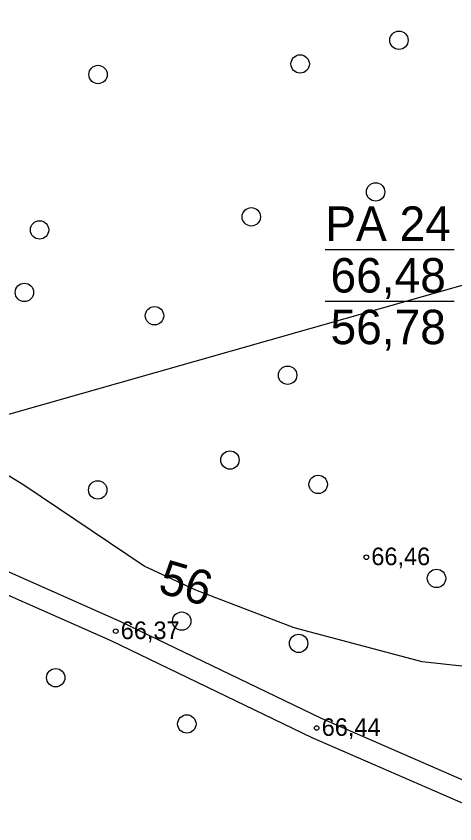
# Model space of a CAD drawing. Extents: x 532503 to 539665, y 6557663 to 6561526.
# Drawn here: x 534640.9 to 534702, y 6559686.6 to 6559799.2 of the extents above; entities that cross this region are included whole.
import ezdxf

# ---------------------------------------------------------------- set-up
doc = ezdxf.new("R2010")
doc.units = 0
for name, color, linetype in [('GEOLPUNKT', 7, 'Continuous'), ('HALJASTUS', 7, 'Continuous'), ('KORGUS-EH2000', 7, 'Continuous'), ('Lamami horisontaal_EH2000', 7, 'Continuous'), ('Lõige', 7, 'Continuous'), ('TEE', 7, 'Continuous')]:
    doc.layers.add(name, color=color, linetype=linetype)

# ---------------------------------------------------------------- blocks, each defined once
blk = doc.blocks.new('METS')
at = {"layer": 'HALJASTUS'}
blk.add_circle((0, 0), 0.8, dxfattribs=at)

msp = doc.modelspace()

# ---------------------------------------------------------------- linework, layer by layer
at = {"layer": 'GEOLPUNKT'}
for p, q in [((534683.91, 6559766.66), (534701.91, 6559766.66)), ((534683.91, 6559759.46), (534701.91, 6559759.46))]:
    msp.add_line(p, q, dxfattribs=at)
at = {"layer": 'KORGUS-EH2000'}
for centre in [(534689.66, 6559723.77), (534654.76, 6559713.47), (534682.74, 6559699.98)]:
    msp.add_circle(centre, 0.32, dxfattribs=at)
at = {"layer": 'Lamami horisontaal_EH2000'}
msp.add_lwpolyline([(534790.42, 6559711.19), (534772.61, 6559709.67), (534754.79, 6559708.12), (534736.98, 6559707), (534719.16, 6559707.01), (534715.24, 6559707.24), (534697.43, 6559709.2), (534679.62, 6559713.92), (534665.92, 6559719.18), (534658.73, 6559722.53), (534641.96, 6559733.8), (534636.15, 6559737.35)], dxfattribs=at)
at = {"layer": 'Lõige'}
msp.add_lwpolyline([(533917.43, 6559650.43), (533949.04, 6559659.85), (534215.74, 6559786.31), (534470.46, 6559695.5), (534707.91, 6559763.06), (534929.16, 6559826.01), (535198.18, 6559814.49), (535305.66, 6559887.85), (535520.8, 6559960.87), (535543.92, 6559971)], dxfattribs=at)
at = {"layer": 'TEE'}
for points in [[(534461.08, 6559790.53), (534478.84, 6559786.97), (534536.82, 6559761.75), (534575.75, 6559749.46), (534599.95, 6559739.48), (534655.41, 6559714.82), (534683.38, 6559701.33), (534712.77, 6559688.53)], [(534713.08, 6559685.13), (534682.1, 6559698.62), (534654.11, 6559712.12), (534625.54, 6559724.78), (534598.72, 6559736.74), (534574.63, 6559746.68), (534535.55, 6559759.03), (534477.79, 6559784.16)]]:
    msp.add_lwpolyline(points, dxfattribs=at)

# ---------------------------------------------------------------- block references
at = {"layer": 'HALJASTUS', "xscale": 1.6, "yscale": 1.6000000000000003}
for p in [(534694.2, 6559795.82), (534680.44, 6559792.51), (534652.3, 6559791.04), (534690.95, 6559774.68), (534673.64, 6559771.21), (534644.15, 6559769.39), (534642.05, 6559760.67), (534660.16, 6559757.42), (534678.69, 6559749.14), (534670.67, 6559737.32), (534682.95, 6559733.92), (534652.26, 6559733.16), (534699.43, 6559720.82), (534663.96, 6559714.87), (534680.23, 6559711.77), (534646.4, 6559706.99), (534664.66, 6559700.54)]:
    msp.add_blockref('METS', p, dxfattribs=at)

# ---------------------------------------------------------------- texts
at = {"layer": 'GEOLPUNKT'}
for s, p in [('PA 24', (534683.94, 6559767.86)), ('66,48', (534684.67, 6559760.66)), ('56,78', (534684.67, 6559753.46))]:
    msp.add_text(s, height=4.8, dxfattribs=at).set_placement(p)
at = {"layer": 'KORGUS-EH2000'}
for s, p in [('66,46', (534690.35, 6559722.67)), ('66,37', (534655.46, 6559712.37)), ('66,44', (534683.44, 6559698.88))]:
    msp.add_text(s, height=2.45, dxfattribs=at).set_placement(p)
at = {"layer": 'Lamami horisontaal_EH2000'}
msp.add_text('56', height=4.8, rotation=343.7133, dxfattribs=at).set_placement((534660.48, 6559718.91))

doc.saveas('drawing.dxf')
